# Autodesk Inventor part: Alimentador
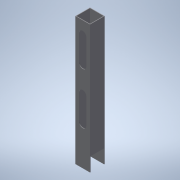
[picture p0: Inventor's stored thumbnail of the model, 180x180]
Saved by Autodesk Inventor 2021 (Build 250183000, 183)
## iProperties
Created: 2021-02
Part Number: Alimentador
Material: Genérico
Document SubType Name: Modeling
Designer: ATOUZA
Density: 1 g/cm^3
Appearance: Valor por defecto
Author: ATOUZA
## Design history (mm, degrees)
sketch "Boceto1"
  geometry: L1 (20.05, 20.05)-(-20.05, 20.05); L2 (-20.05, 20.05)-(-20.05, -20.05); L3 (-20.05, -20.05)-(20.05, -20.05); L4 (20.05, -20.05)-(20.05, 20.05); L5 (20.05, 20.05)-(-20.05, -20.05); L6 (-20.05, 20.05)-(20.05, -20.05); L7 (18.55, 18.55)-(-18.55, 18.55); L8 (-18.55, 18.55)-(-18.55, -18.55); L9 (-18.55, -18.55)-(18.55, -18.55); L10 (18.55, -18.55)-(18.55, 18.55); 1 further point
  constraints: 20 end point, 4 parallel, 2 midpoint, 2 perpendicular, 1 horizontal, 3 other
  dimensions: "d0" = 40.1 distance of L3.end L2.end; "d1" = 40.1 distance of L2.end L1.end; "d2" = 1.5 distance between parallel lines of L4 L10
extrude "Extrusión1" new body sketch "Boceto1" distance "d3" = 350; taper "d4" = 0 deg
sketch "Boceto2"
  geometry: L1 (1.5, 0)-(1.5, 350) reference; L2 (38.6, 0)-(38.6, 350) reference; L3 (1.5, 0)-(38.6, 0); L4 (38.6, 0)-(38.6, 38); L5 (38.6, 38)-(1.5, 38); L6 (1.5, 38)-(1.5, 0); 3 further points
  constraints: 8 end point, 2 parallel, 1 horizontal, 1 perpendicular, 1 point on line
  dimensions: "d5" = 38 distance of L4.end L3.end
extrude "Extrusión2" cut sketch "Boceto2" extent not by distance; stored distance "d6" = 0; taper "d7" = 0 deg
sketch "Boceto3"
  geometry: L1 (20.05, 0)-(20.05, 35); L2 (20.05, 35)-(20, 70); L3 (20, 105)-(20, 140); L4 (20, 140)-(20, 175); L5 (20, 175)-(20, 210); L6 (20, 210)-(20, 245); L7 (20, 245)-(20, 280); L8 (20, 280)-(20, 315); L9 (20, 280)-(20, 315); L10 (20, 175)-(20, 105); L11 (10, 175)-(10, 105); L12 (30, 105)-(30, 175); L13 (20, 315)-(20, 245); L14 (10, 315)-(10, 245); L15 (30, 245)-(30, 315); A1 r 10 centre (20, 175) between (30, 175) and (10, 175); A2 r 10 centre (20, 105) between (10, 105) and (30, 105); A3 r 10 centre (20, 315) between (30, 315) and (10, 315); A4 r 10 centre (20, 245) between (10, 245) and (30, 245)
  constraints: 34 end point, 8 point on circle, 8 tangent, 5 point on line, 4 centre point, 2 collinear, 2 midpoint, 2 parallel, 1 vertical
  dimensions: "d8" = 35 distance of L1.start L1.end; "d9" = 35 distance of L2.end L1.end; "d10" = 35 distance of L3.start L3.end; "d11" = 35 distance of L3.end L4.end; "d12" = 35 distance of L4.end L5.end; "d13" = 35 distance of L5.end L6.end; "d14" = 35 distance of L6.end L7.end; "d15" = 35 distance of L7.end L8.end; "d16" = 35 distance of L9.start L9.end; "d17" = 20 diameter of A2; "d18" = 20 diameter of A4; "d21" = 35 distance of L3.start L2.end
extrude "Extrusión3" cut sketch "Boceto3" extent not by distance; stored distance "d19" = 0; taper "d20" = 0 deg
sketch "Boceto4"
  geometry: L1 (-20.05, 0)-(-20.05, 35); L2 (-20.05, 35)-(-20.05, 70); C1 r 10 at (-20.05, 52.5)
  constraints: 4 end point, 1 centre point, 1 midpoint, 1 point on line, 1 vertical
  dimensions: "d22" = 35 distance of L1.start L1.end; "d23" = 35 distance of L1.end L2.end; "d24" = 20 diameter of C1
extrude "Extrusión4" cut sketch "Boceto4" distance "d25" = 4; taper "d26" = 0 deg
node "Sólido1"
